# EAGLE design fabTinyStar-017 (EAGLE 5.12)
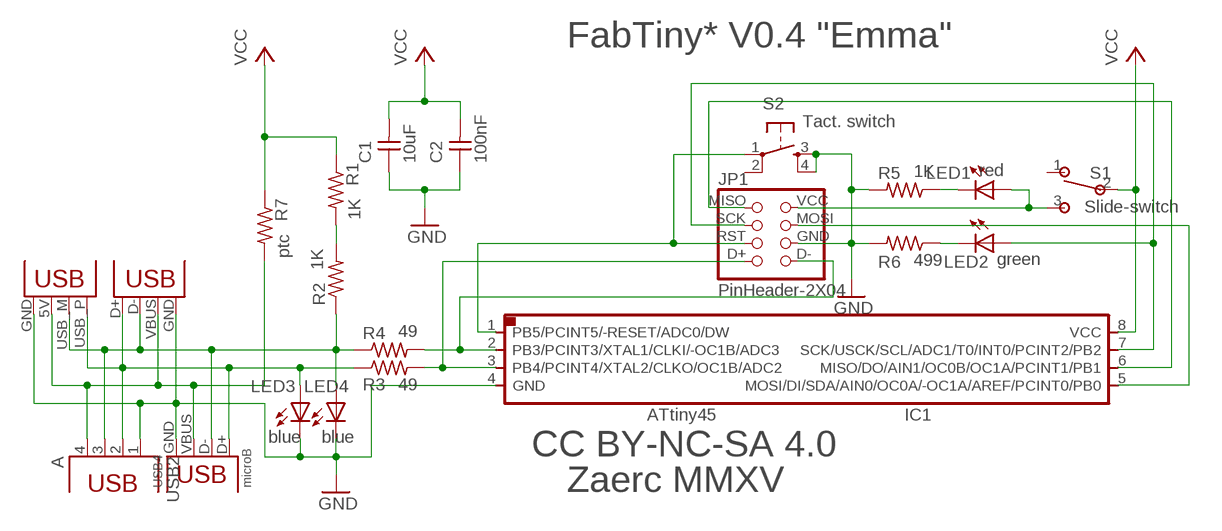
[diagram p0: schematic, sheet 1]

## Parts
C1  10uF  UNPOLARIZED_CAPACITOR1206  [1206]
C2  100nF  UNPOLARIZED_CAPACITOR1206  [1206]
IC1  ATTINY*5  ATTINY45SI  [SOIC8]
JP1  PinHeader-2X04  PINHD-2X4SMD90  [8PAD_EDGE]
LED1  red  LED1206  [1206P]
LED2  green  LED1206  [1206P]
LED3  blue  LED1206  [1206P]
LED4  blue  LED1206  [1206P]
R1  1K  RESISTOR1206  [1206]
R2  1K  RESISTOR1206  [1206]
R3  49  RESISTOR1206  [1206]
R4  49  RESISTOR1206  [1206]
R5  1K  RESISTOR1206  [1206]
R6  499  RESISTOR1206  [1206]
R7  ptc  RESISTOR1206  [1206]
S1  Slide-switch  SLIDE-SWITCH  [AYZ0102AGRLC]
S2  Tact. switch  6MM_SWITCH6MM_SWITCH  [6MM_SWITCH]
USB1  pcb  USBPCB  [USB-A-PCB]
USB2  A  PN87520  [PN87520]
USB3  miniB  USB_MINIB  [USB_MINIB]
USB4  microB  MICRO-USB_1/64  [DX4R005HJ5_64]

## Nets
5V: R7.2 USB1.5V(VBUS) USB2.4 USB3.VBUS USB4.VBUS
B0: IC1.5(MOSI/DI/SDA/AIN0/OC0A/-OC1A/AREF/PCINT0/PB0) JP1.MOSI
B1: IC1.6(MISO/DO/AIN1/OC0B/OC1A/PCINT1/PB1) JP1.MISO
B2: IC1.7(SCK/USCK/SCL/ADC1/T0/INT0/PCINT2/PB2) JP1.SCK LED2.1(A)
B3: IC1.2(PB3/PCINT3/XTAL1/CLKI/-OC1B/ADC3) JP1.D- R4.2
B4: IC1.3(PB4/PCINT4/XTAL2/CLKO/OC1B/ADC2) JP1.D+ R3.2
B5: IC1.1(PB5/PCINT5/-RESET/ADC0/DW) JP1.RST S2.1(P)
D+: LED3.1(A) R3.1 USB1.USB_P(D+) USB2.2 USB3.D+ USB4.D+
D-: LED4.1(A) R2.1 R4.1 USB1.USB_M(D-) USB2.3 USB3.D- USB4.D-
GND: C1.1 C2.1 IC1.4(GND) JP1.GND LED3.2(C) LED4.2(C) R5.2 R6.2 S2.3(S) S2.4(S1) USB1.GND USB2.1 USB3.GND USB4.GND
N$1: R1.2 R2.2
N$2: JP1.VCC LED1.1(A) S1.3
N$13: LED2.2(C) R6.1
N$14: LED1.2(C) R5.1
VCC: C1.2 C2.2 IC1.8(VCC) R1.1 R7.1 S1.2
Unconnected: S1.1 S2.2(P1)

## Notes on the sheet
- FabTiny* V0.4 "Emma"
- CC BY-NC-SA 4.0
- Zaerc MMXV

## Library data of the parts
C1 C2 = 01_FAB_Hello:UNPOLARIZED_CAPACITOR: unpolarized_capacitor
IC1 = 01_fab:ATTINY45
JP1 = Zaerc:PINHD-2X4: PIN HEADER
LED1-LED4 = 01_FAB_Hello:LED
R1-R7 = 01_FAB_Hello:RESISTOR
S1 = Zaerc:SLIDE-SWITCH
S2 = 01_fab:6MM_SWITCH: OMRON SWITCH
USB1 = SparkFun:USB: USB Connectors USB-B-PTH is fully proven SKU : PRT-00139 USB-miniB is fully proven SKU : PRT-00587 USB-A-PCB is untested. USB-A-H is throughly reviewed, but untested. Spark Fun Electronics SKU : PRT-00437 USB-B-SMT is throughly reviewed, but untested. Needs silkscreen touching up. USB-A-S has not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
USB2 = Zaerc:PN87520: BERG USB connector
USB3 = 01_fab:USB_MINIB
USB4 = Zaerc:MICRO-USB

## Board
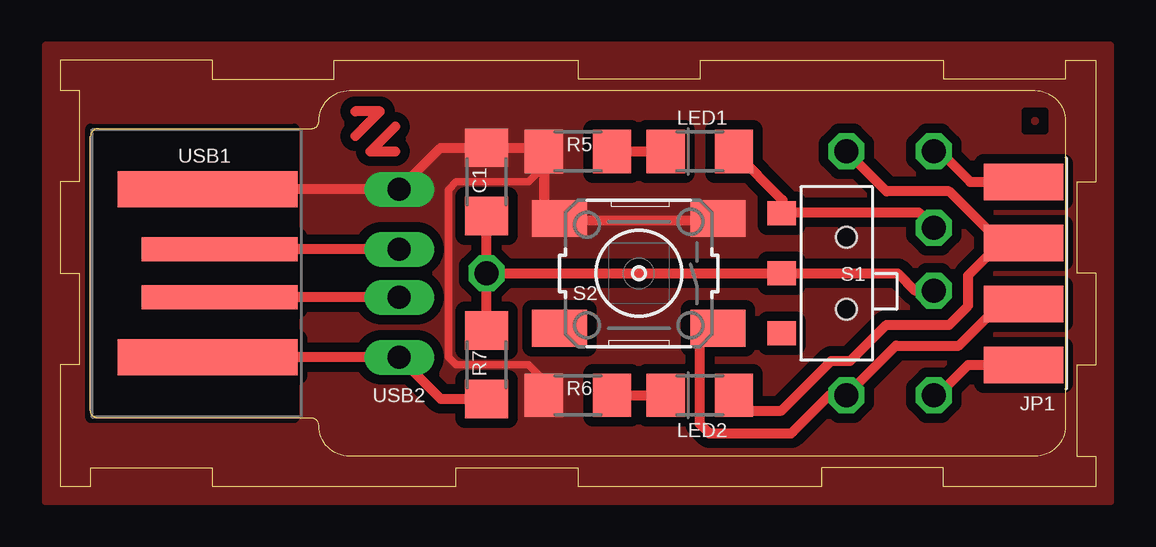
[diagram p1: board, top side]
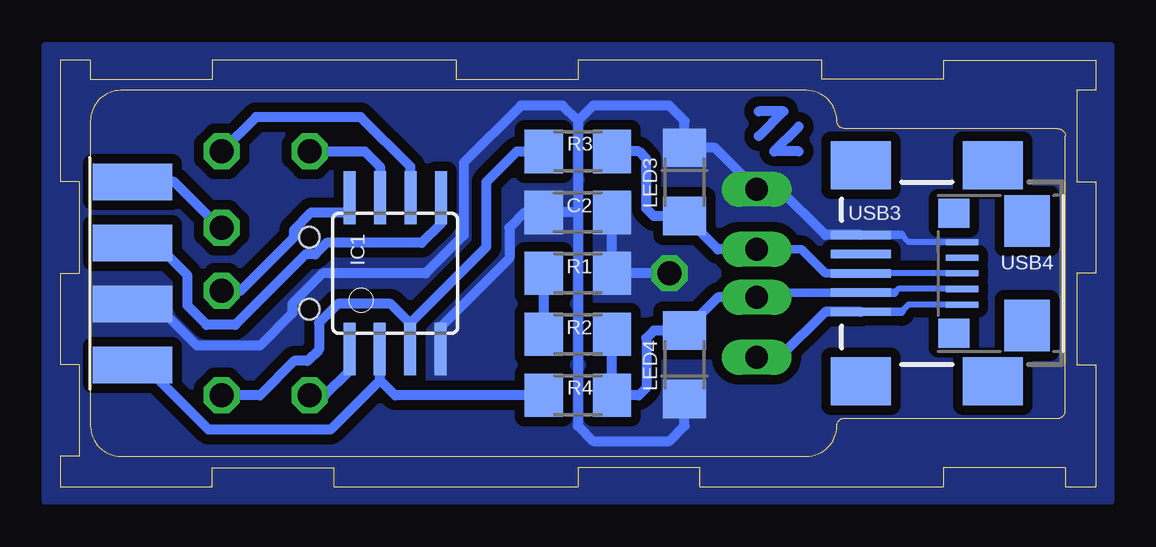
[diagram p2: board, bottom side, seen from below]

Size 43.18 x 17.78 mm. Coordinates in mm from the lower left corner, seen from the top.
Outline: 10.48,14.92 arc90 10.79,15.24 arc-90 12.06,16.51 40.64,16.51 arc-90 41.91,15.24 41.91,2.54 arc-90 40.64,1.27 12.06,1.27 arc-90 10.79,2.54 arc90 10.48,2.86 1.59,2.86 arc-90 1.27,3.17 1.27,14.61 arc-90 1.59,14.92 10.48,14.92
Outline: 0,17.78 0,16.51 0.79,16.51 0.79,12.7 0,12.7 0,8.89 0.79,8.89 0.79,5.08 0,5.08 0,0 1.27,0 1.27,0.79 6.35,0.79 6.35,0 16.51,0 16.51,0.79 21.59,0.79 21.59,0 31.75,0 31.75,0.79 36.83,0.79 36.83,0 43.18,0 43.18,1.27 42.39,1.27 42.39,5.08 43.18,5.08 43.18,8.89 42.39,8.89 42.39,12.7 43.18,12.7 43.18,17.78 41.91,17.78 41.91,16.99 36.83,16.99 36.83,17.78 26.67,17.78 26.67,16.99 21.59,16.99 21.59,17.78 11.43,17.78 11.43,16.99 6.35,16.99 6.35,17.78 0,17.78
Copper layers (1*16): Top 0.035mm / dielectric 1.5mm / Bottom 0.035mm
Design rules "default *": minimum track width 10mil, minimum drill 0.7938mm, track to track 16mil, track to pad 16mil, pad to pad 16mil, via to via 16mil, smd to smd 16mil, copper to edge 0mil, drill to drill 8mil, minimum pad ring 10mil, minimum via ring 8mil, stop-mask expansion 4mil, vias tented up to drill 0mil, thermal gap 10mil
tRestrict: area 1.3,2.9 to 9.8,14.9

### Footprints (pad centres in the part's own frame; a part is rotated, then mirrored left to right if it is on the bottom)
1206 = smd 1.6 x 1.803: 1 -1.422,0; 2 1.422,0
SOIC8 = smd 0.5 x 2.2: 1 -1.905,-3.154; 2 -0.645,-3.154; 3 0.625,-3.154; 4 1.895,-3.154; 5 1.905,3.154; 6 0.635,3.154; 7 -0.635,3.154; 8 -1.905,3.154
8PAD_EDGE = smd 1.524 x 3.302: D+ 3.81,0; MISO -3.81,0; RST 1.27,0; SCK -1.27,0 | smd 1.524 x 3.302 bottom: D- 3.81,0; GND 1.27,0; MOSI -1.27,0; VCC -3.81,0
1206P = smd 1.6 x 1.803: 1 -1.422,0; 2 1.422,0
AYZ0102AGRLC = smd 1 x 1.2: 1 2.5,-2.3; 2 0,-2.3; 3 -2.5,-2.3 | hole 0.85: -1.5,0.4; 1.5,0.4
6MM_SWITCH = smd 2.286 x 1.524: 1 -3.302,2.286; 2 3.302,2.286; 3 -3.302,-2.286; 4 3.302,-2.286
USB-A-PCB = smd 7.5 x 1.5: 5V -0.2,-3.5; GND -0.2,3.5 | smd 6.5 x 1: USB_M 0.3,-1; USB_P 0.3,1
PN87520 = drill 0.95 long: 1 -3.5,2.71; 2 -1,2.71; 3 1,2.71; 4 3.5,2.71
USB_MINIB = smd 2.5 x 0.35: D+ 3.77,0; D- 3.77,0.8; GND 3.77,-1.6; ID 3.77,-0.8; VBUS 3.77,1.6 | smd 2.5 x 2: GND@1 -1.73,-4.5; GND@2 -1.73,4.5; GND@3 3.77,4.5; GND@4 3.77,-4.5
DX4R005HJ5_64 = smd 0.254 x 1.35: D+ 0,1.6; D- -0.65,1.6; GND 1.3,1.6; ID 0.65,1.6; VBUS -1.3,1.6 | smd 1.2 x 1.3: GND@1 -2.5,1.95; GND@2 2.5,1.95 | smd 2.15 x 1.9: GND@3 -2.175,-1.1; GND@4 2.175,-1.1

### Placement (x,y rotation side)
C1  17.78,12.7 270 top
C2  21.59,11.43 0 bottom
IC1  29.21,8.89 0 bottom
JP1  40.16,8.89 270 top
LED1  26.67,13.97 180 top
LED2  26.67,3.81 180 top
LED3  17.15,12.7 90 bottom
LED4  17.14,5.08 270 bottom
R1  21.59,8.89 180 bottom
R2  21.59,6.35 180 bottom
R3  21.59,13.97 180 bottom
R4  21.59,3.81 180 bottom
R5  21.59,13.97 180 top
R6  21.59,3.81 180 top
R7  17.78,5.08 270 top
S1  32.38,8.89 270 top
S2  24.13,8.89 180 top
USB1  6.35,8.89 0 top
USB2  11.43,8.89 270 top
USB3  6.03,8.89 180 bottom
USB4  3.97,8.89 90 bottom

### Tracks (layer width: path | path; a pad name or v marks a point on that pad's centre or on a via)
5V
  Top 0.406: USB1.5V USB2.4 15.87,3.66 R7.2
  Bottom 0.254: USB4.VBUS 7.81,7.59 8.11,7.29
  Bottom 0.356: 8.11,7.29 USB3.VBUS
  Bottom 0.406: USB3.VBUS 11.28,7.29 13.18,5.39 USB2.4
B0
  Bottom 0.406: IC1.5 | IC1.5 27.3,10.95 28.1,10.16 32.07,10.16 32.54,9.68 32.94,9.68 35.88,6.75 37.07,6.75 37.86,7.54 37.86,8.81 39.21,10.16 JP1.MOSI
B1  (via drill 1)
  Top 0.406: v36.43,13.97 36.67,13.97 37.94,12.7 JP1.MISO
  Bottom 0.406: IC1.6 28.57,13.34 30.64,15.4 35,15.4 v36.43,13.97
B2  (via drill 1)
  Top 0.406: v32.78,13.97 | v32.78,13.97 34.45,12.3 37.07,12.3 39.21,10.16 | LED2.1 28.57,3.33 28.57,3.17 30.08,3.17 32.15,5.24 32.94,5.24 34.45,6.75 37.07,6.75 37.86,7.54 37.86,8.81 39.21,10.16 | 39.21,10.16 JP1.SCK | 39.21,10.16
  Bottom 0.406: IC1.7 29.84,13.34 30.48,13.97 v32.78,13.97 | IC1.7
B3
  Bottom 0.406: R4.2 29.21,3.81 29.84,4.45 | 29.84,4.45 29.84,5.73 IC1.2 | 29.84,4.45 31.91,2.38 36.99,2.38 39.69,5.08 JP1.D-
B4  (via drill 1)
  Top 0.406: v36.43,3.81 36.59,3.81 37.86,5.08 JP1.D+
  Bottom 0.406: R3.2 24.13,13.97 25.4,12.7 25.4,10 28.59,6.82 | 28.59,6.82 IC1.3 28.57,5.73 | 28.59,6.82 29.39,7.62 31.59,7.62 32.38,6.83 32.38,5.71 32.86,5.24 33.42,5.24 34.85,3.81 v36.43,3.81
B5  (via drill 1)
  Top 0.406: S2.1 26.67,6.6 26.67,2.62 27.07,2.22 30.48,2.22 32.07,3.81 v32.78,3.81 34.85,5.87 37.47,5.87 39.21,7.62 JP1.RST
  Bottom 0.406: IC1.1 31.11,4.84 32.15,3.81 v32.78,3.81
D+
  Top 0.406: USB2.2 USB1.USB_P
  Bottom 0.254: USB4.D+ USB3.D+
  Bottom 0.305: USB3.D+
  Bottom 0.356: USB2.2 12.27,9.89 11.27,8.89 USB3.D+
  Bottom 0.406: R3.1 19.05,13.97 18.73,13.65 18.73,11.59 18.42,11.28 LED3.1 15.76,9.89 USB2.2
D-
  Top 0.406: USB2.3 USB1.USB_M
  Bottom 0.254: USB4.D- 8.24,8.24 8.39,8.09
  Bottom 0.305: 13.94,8.09 USB2.3
  Bottom 0.356: 13.94,8.09 USB3.D- 8.39,8.09
  Bottom 0.406: R2.1 R4.1 19.05,3.81 18.73,4.13 18.73,6.19 18.42,6.5 LED4.1 15.76,7.89 USB2.3
GND
  Top 0.305: 20.17,13.34 19.53,12.7 16.51,12.7 16.19,12.38 16.19,5.4 16.51,5.08 19.53,5.08 20.17,4.44 R6.2 | R6.2
  Top 0.406: USB2.1 USB1.GND | USB2.1 | USB2.1 15.87,14.12 C1.1 20.02,14.12 R5.2 20.17,13.34 20.17,11.84 S2.4 20.95,11.11 27.3,11.11 S2.3
  Bottom 0.254: USB4.GND 7.81,10.19 8.11,10.49
  Bottom 0.356: 8.11,10.49 USB3.GND
  Bottom 0.406: 21.59,15.24 20.95,15.88 17.78,15.88 17.14,15.24 LED3.2 | 21.59,11.43 C2.1 | C2.1 | 21.59,15.24 21.59,11.43 | 21.59,11.43 | 21.59,11.43 21.59,2.54 20.95,1.91 17.78,1.91 17.14,2.54 LED4.2 | 21.59,11.43 | IC1.4 27.3,6.03 27.3,6.67 24.45,9.53 24.45,10.79 23.81,11.43 C2.1 | JP1.GND 39.21,7.62 37.47,5.87 34.85,5.87 33.5,7.22 33.5,7.62 32.23,8.89 27.94,8.89 26.35,10.48 26.35,13.49 23.97,15.88 22.23,15.88 21.59,15.24 | 21.59,15.24 | USB3.GND 11.28,10.49 13.18,12.39 USB2.1 15.87,14.12 LED3.2 | LED3.2
  pour Top (rank 6, no thermals): -0.64,-0.63 43.81,-0.63 43.81,18.41 -0.64,18.41
  pour Bottom (rank 2, no thermals): -0.64,-0.64 43.81,-0.64 43.81,18.41 -0.64,18.41
N$1
  Bottom 0.406: R2.2 R1.2
N$2  (via drill 1)
  Top 0.406: 30.12,11.43 S1.3 | 30.12,11.43 30.12,11.94 LED1.1 | 30.12,11.43 35.8,11.43 v36.43,10.79
  Bottom 0.406: JP1.VCC 38.42,12.7 36.51,10.79 v36.43,10.79
N$3
  pour Top: 40.64,15.08 40.64,15.08 arc90 40.8,15.24 arc90 40.64,15.4 arc90 40.48,15.24 40.48,15.24 arc90
N$4
  Bottom 0.406: 14.05,15.64 13.02,15.64 14.05,14.61
N$5
  Bottom 0.406: 12.38,15 13.41,13.97 12.38,13.97
N$13
  Top 0.406: R6.1 LED2.2 | LED2.2
N$14
  Top 0.406: R5.1 25.09,13.97 LED1.2
N$33
  Top 0.406: 12.3,15.64 13.34,15.64 12.3,14.61
N$34
  Top 0.406: 13.97,15 12.94,13.97 13.97,13.97
VCC  (via drill 1)
  Top 0.406: R7.1 v17.78,8.89 | v17.78,8.89 C1.2 | v17.78,8.89 S1.2 34.92,8.89 35.64,8.18 v36.43,8.18
  Bottom 0.406: v17.78,8.89 R1.1 C2.2 | 31.11,11.43 IC1.8 | 31.11,11.43 | 31.11,11.43 32.7,11.43 33.42,10.72 33.42,10.4 35.64,8.18 v36.43,8.18
  pour Bottom (no thermals): 20.95,5.71 18.41,5.71 15.24,8.89 18.41,12.06 20.95,12.06

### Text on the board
bDocu: FabTiny* v0.4 | CC BY-NC-SA 4.0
